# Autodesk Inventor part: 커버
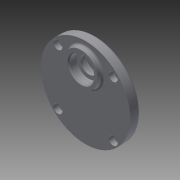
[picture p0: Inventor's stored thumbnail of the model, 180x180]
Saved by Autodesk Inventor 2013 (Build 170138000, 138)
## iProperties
Created: 2015-07
Part Number: 커버
Material: 일반
Document SubType Name: Modeling
Designer: user
Density: 1 g/cm^3
Author: user
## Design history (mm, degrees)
sketch "스케치1"
  geometry: C1 r 40 at (0, 0); 1 further point
  constraints: 1 centre point, 1 coincident
  dimensions: "d0" = 80 diameter of C1
extrude "돌출1" new body sketch "스케치1" distance "d1" = 9; taper "d2" = 0 deg
sketch "스케치2"
  geometry: L1 (0, 0)-(0, 11); L2 (0, 0)-(0, -20); L3 (0, 0)-(20, 0); C1 r 40 at (0, 0) reference; C2 r 14 at (0, 11); C3 r 14 at (0, -20)
  constraints: 6 end point, 2 centre point, 2 coincident, 1 collinear, 1 horizontal, 1 perpendicular, 1 vertical
  dimensions: "d3" = 11 distance of L1.start L1.end; "d4" = 20 distance of L1.start L2.end; "d5" = 90 deg angle of L2 L3 (derived); "d6" = 28 diameter of C2; "d7" = 28 diameter of C3
extrude "돌출2" join sketch "스케치2" distance "d8" = 3; taper "d9" = 0 deg
sketch "스케치3"
  geometry: L1 (0, 0)-(0, 20); L2 (0, 0)-(20, 0); C1 r 40 at (0, 0) reference; C2 r 15 at (0, 20)
  constraints: 4 end point, 1 centre point, 1 coincident, 1 horizontal, 1 perpendicular, 1 vertical
  dimensions: "d10" = 20 distance of L1.start L1.end; "d11" = 90 deg angle of L2 L1 (derived); "d12" = 30 diameter of C2
extrude "돌출3" join sketch "스케치3" distance "d13" = 4; taper "d14" = 0 deg
sketch "스케치4"
  geometry: C1 r 15 at (0, 0) reference; C2 r 7.5 at (0, 0); 1 further point
  constraints: 1 centre point, 1 coincident
  dimensions: "d15" = 15 diameter of C2
extrude "돌출4" cut sketch "스케치4" distance "d16" = 4123; taper "d17" = 0 deg
sketch "스케치5"
  geometry: C1 r 7.5 at (0, 0) reference; C2 r 15 at (0, 0) reference; C3 r 11 at (0, 0); 1 further point
  constraints: 1 centre point, 1 coincident
  dimensions: "d18" = 22 diameter of C3
extrude "돌출5" cut sketch "스케치5" distance "d19" = 7; taper "d20" = 0 deg
sketch "스케치6"
  geometry: C1 r 7.5 at (0, 0) reference; C2 r 14 at (0, 0) reference; C3 r 11 at (0, 0); 1 further point
  constraints: 1 centre point, 1 coincident
  dimensions: "d21" = 22 diameter of C3
extrude "돌출6" cut sketch "스케치6" distance "d22" = 7; taper "d23" = 0 deg
sketch "스케치7"
  geometry: C1 r 14 at (0, 0) reference; C2 r 11 at (0, 0); 1 further point
  constraints: 1 centre point, 1 coincident
  dimensions: "d24" = 22 diameter of C2
extrude "돌출7" cut sketch "스케치7" distance "d25" = 7; taper "d26" = 0 deg
sketch "스케치8"
  geometry: C1 r 9 at (0, 0); 2 further points
  constraints: 1 centre point, 1 coincident, 1 vertical alignment
  dimensions: "d27" = 18 diameter of C1
extrude "돌출8" cut sketch "스케치8" distance "d28" = 1; taper "d29" = 0 deg
chamfer "모따기1" distance "d30" = 1; stored, may be unused: second distance "d31" = 2, angle "d32" = 45 deg
fillet "모깎기1" dims "d33" = 0.3
fillet "모깎기2" dims "d34" = 2
fillet "모깎기4" dims "d36" = 2
fillet "모깎기5" dims "d37" = 2
sketch "스케치9" dims "d38" = 70
  geometry: L1 (0, 0)-(24.749, 24.749); L2 (0, 0)-(35, 0); C1 r 40 at (0, 0) reference; 4 further points
  constraints: 4 end point, 2 coincident, 1 equal length, 1 horizontal, 8 other
  dimensions: "d39" = 45 deg angle of L2 L1; "d42" = 360 deg dimension on L1.start point (24.749, 24.749) (derived)
hole "구멍1" sketch "스케치9" at (24.749, 24.749), (-24.749, 24.749), (-24.749, -24.749), (24.749, -24.749) diameter "d44" = 4.5; stored, may be unused: countersink angle "d48" = 90 deg, drill point angle "d50" = 118 deg; dims "d45" = 6, "d46" = 8, "d47" = 4.4, "d49" = 8
node "솔리드1"
